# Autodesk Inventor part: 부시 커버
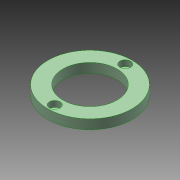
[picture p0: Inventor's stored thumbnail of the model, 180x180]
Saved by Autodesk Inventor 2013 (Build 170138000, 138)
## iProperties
Created: 2023-09
Part Number: 부시 커버
Material: 강철, 연강
Document SubType Name: Modeling
Designer: mdu-01
Density: 1 g/cm^3
Author: mdu-01
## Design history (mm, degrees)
sketch "스케치1"
  geometry: C1 r 20 at (0, 0); C2 r 31 at (0, 0); 1 further point
  constraints: 2 centre point, 2 coincident
  dimensions: "d0" = 40 diameter of C1; "d1" = 62 diameter of C2
extrude "돌출1" new body sketch "스케치1" distance "d2" = 7; taper "d3" = 0 deg
sketch "스케치2"
  geometry: C1 r 22.5 at (0, 0); 2 further points
  constraints: 2 vertical alignment, 1 centre point, 1 coincident, 2 other
  dimensions: "d4" = 45 diameter of C1; "d6" = 3.5 dimension on C1
hole "구멍1" sketch "스케치2" at (0, 26) diameter "d7" = 4.5; stored, may be unused: countersink angle "d11" = 90 deg, drill point angle "d13" = 118 deg; dims "d8" = 6, "d9" = 8, "d10" = 4.4, "d12" = 8
node "솔리드1"
pattern_circular "원형 패턴1" dims angle "d15" = 360 deg
